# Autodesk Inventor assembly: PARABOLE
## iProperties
Author: MARRO MONGOUACHON
Comments: LYCEE ANDRE MALRAUX 77130 MONTEREAU
Title: PARABOLE
Shininess: 64.0
Length Units: 11269
Angle Units: 11279
Time Units: 11290
Mass Units: 11283
Length Display Precision: 3
Angle Display Precision: 2
Compacted: True
Created: 2003-02
Part Number: parabole spécial motion inventor
Document SubType Name: Assembly
Designer: Maison
Density: 0.0
Volumn: 0.0
Area: 0.0
PropertySet Name: Model Information
Control State: 0
Master: False
Checked Out: False
Author: Maison
